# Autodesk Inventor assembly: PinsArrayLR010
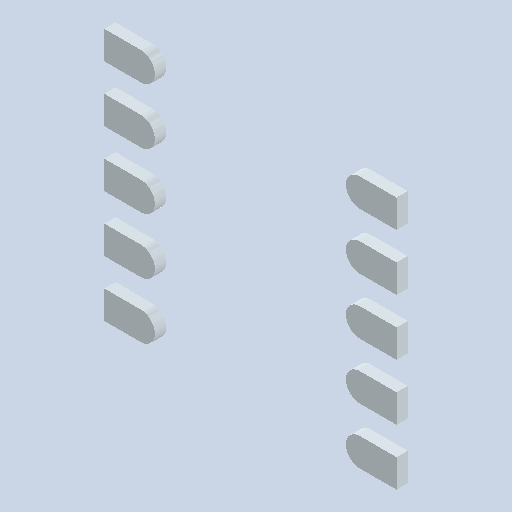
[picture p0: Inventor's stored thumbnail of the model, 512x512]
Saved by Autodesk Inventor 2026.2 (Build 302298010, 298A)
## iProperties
Created: 2026-10
Part Number: PinsArrayLR010
Document SubType Name: Assembly
Designer: mel
Author: mel
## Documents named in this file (11)
- D:\travail\année 2026-2027\1 sti2d IT\poubelle à verre\raspberry-pico-2-microcontroller-rp2350-1.snapshot.5\raspberry_pico_2\raspberry_pico_2\PinsArrayLR010.iam
- D:\travail\année 2026-2027\1 sti2d IT\poubelle à verre\raspberry-pico-2-microcontroller-rp2350-1.snapshot.5\raspberry_pico_2\raspberry_pico_2\PinsArrayLR.ipt
- D:\travail\année 2026-2027\1 sti2d IT\poubelle à verre\raspberry-pico-2-microcontroller-rp2350-1.snapshot.5\raspberry_pico_2\raspberry_pico_2\PinsArrayLR001.ipt
- D:\travail\année 2026-2027\1 sti2d IT\poubelle à verre\raspberry-pico-2-microcontroller-rp2350-1.snapshot.5\raspberry_pico_2\raspberry_pico_2\PinsArrayLR002.ipt
- D:\travail\année 2026-2027\1 sti2d IT\poubelle à verre\raspberry-pico-2-microcontroller-rp2350-1.snapshot.5\raspberry_pico_2\raspberry_pico_2\PinsArrayLR003.ipt
- D:\travail\année 2026-2027\1 sti2d IT\poubelle à verre\raspberry-pico-2-microcontroller-rp2350-1.snapshot.5\raspberry_pico_2\raspberry_pico_2\PinsArrayLR004.ipt
- D:\travail\année 2026-2027\1 sti2d IT\poubelle à verre\raspberry-pico-2-microcontroller-rp2350-1.snapshot.5\raspberry_pico_2\raspberry_pico_2\PinsArrayLR005.ipt
- D:\travail\année 2026-2027\1 sti2d IT\poubelle à verre\raspberry-pico-2-microcontroller-rp2350-1.snapshot.5\raspberry_pico_2\raspberry_pico_2\PinsArrayLR006.ipt
- D:\travail\année 2026-2027\1 sti2d IT\poubelle à verre\raspberry-pico-2-microcontroller-rp2350-1.snapshot.5\raspberry_pico_2\raspberry_pico_2\PinsArrayLR007.ipt
- D:\travail\année 2026-2027\1 sti2d IT\poubelle à verre\raspberry-pico-2-microcontroller-rp2350-1.snapshot.5\raspberry_pico_2\raspberry_pico_2\PinsArrayLR008.ipt
- D:\travail\année 2026-2027\1 sti2d IT\poubelle à verre\raspberry-pico-2-microcontroller-rp2350-1.snapshot.5\raspberry_pico_2\raspberry_pico_2\PinsArrayLR009.ipt
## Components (10 placed, 10 different names)
1. 2761
2. 2762
3. 2763
4. 2764
5. 2765
6. 2766
7. 2767
8. 2768
9. 2769
10. 2770
